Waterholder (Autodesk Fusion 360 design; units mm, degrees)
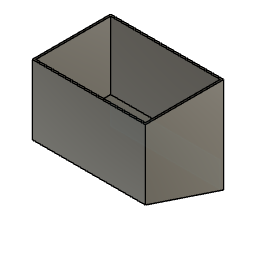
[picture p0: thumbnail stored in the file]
box_primitive "BoxPrimitive1" DistanceX 90 DistanceY 130 DistanceZ 80 OffsetDistanceX 0 OffsetDistanceY 0
shell "Shell1" innerThickness 2
box_primitive "BoxPrimitive2" DistanceX 90 DistanceY 130 DistanceZ 30 OffsetDistanceX 0 OffsetDistanceY 0
sketch "Sketch4" plane through (0, 0, 0) normal (-1, 0, 0) x axis (0, -1, 0)
  line L1 (-90, -30) -> (-90, 80)
  line L2 (0, -30) -> (-90, -30)
  line L3 (0, 80) -> (0, -30)
  line L4 (-90, 80) -> (0, 80)
  line L5 (-90, -30) -> (0, 0)
  line L6 (-90, -30) -> (0, -30)
  line L7 (0, 0) -> (0, -30)
  point P3 (-90, -30)
  point P8 (-90, -30)
  point P4 (0, -30)
  point P9 (0, -30)
  point P1 (0, 0)
  point P7 (0, 0)
  coincident P3 P8
  coincident P4 P9
  coincident P1 P7
extrude "Extrude1" cut sketch "Sketch4" profile of L2 L5 L6 L7 against normal blind 135
shell "Shell2" innerThickness 2
sketch "Sketch6" plane through (0, 88, 0) normal (0, -1, 0) x axis (1, 0, 0)
  line L1 (2, 0) -> (128, 0)
  line L2 (2, -29.3333) -> (2, 0)
  line L3 (128, -29.3333) -> (2, -29.3333)
  line L4 (128, 0) -> (128, -29.3333)
sketch "Sketch7" plane through (0, 88, 0) normal (0, -1, 0) x axis (1, 0, 0)
  line L1 (25, -20) -> (25, -30)
  line L2 (2.4928, -20) -> (25, -20)
  line L3 (110, -20) -> (2.4928, -20)
  vertical L1
  perpendicular L1 L2
  parallel L2 L3
hole "Hole1" HoleDepth 10 HoleDiameter 6 TipAngle 180
rectangular_pattern "R-Pattern1" uSpaceDistance 90 vSpaceDistance 0
work_plane "WorkPlane1"
work_plane "WorkPlane2"
work_plane "WorkPlane3"
sketch "Sketch8" plane through (97, 45, 25) normal (1, 0, 0) x axis (0, 1, 0)
  line L1 (45, -55) -> (45, -25)
  line L2 (-45, -25) -> (45, -55)
  line L3 (45, -25) -> (-45, -25)
  vertical L1
  perpendicular L1 L3
extrude "Extrude2" add sketch "Sketch8" against normal blind 10
sketch "Sketch9" plane through (32, 45, 25) normal (-1, 0, 0) x axis (0, 1, 0)
  line L1 (45, 25) -> (-45, 25)
  line L2 (45, 55) -> (45, 25)
  line L3 (-45, 25) -> (45, 55)
  horizontal L1
  perpendicular L1 L2
extrude "Extrude3" add sketch "Sketch9" against normal blind 10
